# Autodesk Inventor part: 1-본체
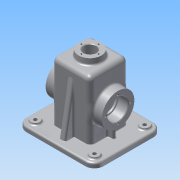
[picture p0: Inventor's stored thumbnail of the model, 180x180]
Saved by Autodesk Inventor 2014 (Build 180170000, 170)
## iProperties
Created: 2015-12
Part Number: 1-본체
Material: 알루미늄 6061
Document SubType Name: Modeling
Designer: Administrator
Density: 2.71 g/cm^3
Appearance: 알루미늄 - 평지
Mass: 804.933 g
Surface Area: 913.236 cm^2
Volume: 297.023 cm^3
Author: Administrator
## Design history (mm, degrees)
sketch "스케치1"
  geometry: L1 (-65, 57.5)-(65, 57.5); L2 (65, 57.5)-(65, -57.5); L3 (65, -57.5)-(-65, -57.5); L4 (-65, -57.5)-(-65, 57.5); L5 (-65, 57.5)-(65, -57.5); L6 (65, 57.5)-(-65, -57.5); 1 further point
  constraints: 12 end point, 2 midpoint, 2 parallel, 1 horizontal, 1 perpendicular
  dimensions: "d0" = 130 distance of L2.end L3.end; "d1" = 115 distance of L1.end L2.end
extrude "돌출1" new body sketch "스케치1" distance "d2" = 8; taper "d3" = 0 deg
sketch "스케치2"
  geometry: L1 (-60, 52.5)-(60, 52.5); L2 (60, 52.5)-(60, -52.5); L3 (60, -52.5)-(-60, -52.5); L4 (-60, -52.5)-(-60, 52.5); L5 (-60, 52.5)-(60, -52.5); L6 (60, 52.5)-(-60, -52.5); 1 further point
  constraints: 12 end point, 2 midpoint, 2 parallel, 1 horizontal, 1 perpendicular
  dimensions: "d4" = 120 distance of L2.end L3.end; "d5" = 105 distance of L1.end L2.end
extrude "돌출2" join sketch "스케치2" distance "d6" = 2; taper "d7" = 0 deg
sketch "스케치3"
  geometry: C1 r 7.5 at (-50, 42.5); C2 r 7.5 at (50, 42.5); 1 further point
  constraints: 2 centre point
  dimensions: "d8" = 15 diameter of C1; "d9" = 15 diameter of C2; "d12" = 42.5 vertical distance of C2.centre point (0, 0); "d13" = 50 horizontal distance of point (0, 0) C2.centre; "d14" = 50 horizontal distance of point (0, 0) C1.centre; "d15" = 42.5 vertical distance of point (0, 0) C1.centre
extrude "돌출3" join sketch "스케치3" distance "d16" = 3; taper "d17" = 0 deg
sketch "스케치4"
  geometry: C1 r 7.5 at (0, 0) reference; C2 r 3 at (0, 0); 1 further point
  constraints: 1 centre point, 1 coincident
  dimensions: "d18" = 6 diameter of C2
extrude "돌출4" cut sketch "스케치4" distance "d19" = 20; taper "d20" = 0 deg
sketch "스케치5"
  geometry: C1 r 7.5 at (0, 0) reference; C2 r 3 at (0, 0); 1 further point
  constraints: 1 centre point, 1 coincident
  dimensions: "d21" = 6 diameter of C2
extrude "돌출5" cut sketch "스케치5" distance "d22" = 20; taper "d23" = 0 deg
sketch "스케치6"
  geometry: L1 (-32.5, 32.5)-(32.5, 32.5); L2 (32.5, 32.5)-(32.5, -32.5); L3 (32.5, -32.5)-(-32.5, -32.5); L4 (-32.5, -32.5)-(-32.5, 32.5); L5 (-32.5, 32.5)-(32.5, -32.5); L6 (32.5, 32.5)-(-32.5, -32.5); 1 further point
  constraints: 12 end point, 2 midpoint, 2 parallel, 1 horizontal, 1 perpendicular
  dimensions: "d24" = 65 distance of L2.end L3.end; "d25" = 65 distance of L1.end L2.end
extrude "돌출6" join sketch "스케치6" distance "d26" = 100; taper "d27" = 0 deg
sketch "스케치7"
  geometry: C1 r 20 at (0, 0); 1 further point
  constraints: 1 centre point, 1 coincident
  dimensions: "d28" = 40 diameter of C1
extrude "돌출7" join sketch "스케치7" distance "d29" = 10; taper "d30" = -5 deg
sketch "스케치8"
  geometry: L1 (-10, -20)-(-10, 85) reference; L2 (-8, 90)-(0, 90) reference; C1 r 27.5 at (45, 32.5); 1 further point
  constraints: 1 centre point
  dimensions: "d31" = 55 diameter of C1; "d32" = 55 distance from line of C1.centre L1; "d34" = 57.5 distance from line of C1.centre L2
extrude "돌출8" join sketch "스케치8" distance "d35" = 15; taper "d36" = 0 deg
sketch "스케치9"
  geometry: L1 (8, 90)-(0, 90) reference; L2 (10, 85)-(10, -20) reference; C1 r 27.5 at (-45, 32.5); 1 further point
  constraints: 1 centre point
  dimensions: "d37" = 55 diameter of C1; "d38" = 57.5 distance from line of C1.centre L1; "d39" = 55 distance from line of L2 C1.centre
extrude "돌출9" join sketch "스케치9" distance "d40" = 15; taper "d41" = 0 deg
fillet "모깎기5" dims "d99" = 3
sketch "스케치10"
  geometry: L1 (57.5, 8)-(57.5, 0) reference; L2 (57.5, 0)-(52.5, 0) reference; L3 (52.5, 0)-(52.5, -2) reference; L4 (52.5, -2)-(-52.5, -2) reference; L5 (-52.5, -2)-(-52.5, 0) reference; L6 (-52.5, 0)-(-57.5, 0) reference; L7 (-57.5, 0)-(-57.5, 8) reference; L8 (-57.5, 8)-(-32.5, 8) reference; L9 (-32.5, 8)-(-32.5, 108) reference; L10 (-32.5, 108)-(-20, 108) reference; L11 (-20, 108)-(-19.125, 118) reference; L12 (-19.125, 118)-(19.125, 118) reference; L13 (19.125, 118)-(20, 108) reference; L14 (20, 108)-(32.5, 108) reference; L15 (32.5, 108)-(32.5, 8) reference; L16 (32.5, 8)-(57.5, 8) reference; L17 (-47.5, 8)-(-32.5, 93.069); 1 further point
  constraints: 2 end point, 2 point on line
  dimensions: "d42" = 10 distance from line of L17.start L7; "d43" = 100 deg angle of L17 L8
extrude "돌출10" join sketch "스케치10" stored distance "d44" = 10; taper "d45" = 0 deg
sketch "스케치11"
  geometry: L1 (-27.5, 27.5)-(27.5, 27.5); L2 (27.5, 27.5)-(27.5, -27.5); L3 (27.5, -27.5)-(-27.5, -27.5); L4 (-27.5, -27.5)-(-27.5, 27.5); L5 (-27.5, 27.5)-(27.5, -27.5); L6 (27.5, 27.5)-(-27.5, -27.5); 1 further point
  constraints: 12 end point, 2 midpoint, 2 parallel, 1 horizontal, 1 perpendicular
  dimensions: "d46" = 55 distance of L2.end L3.end; "d47" = 55 distance of L1.end L2.end
extrude "돌출11" cut sketch "스케치11" distance "d48" = 110; taper "d49" = 0 deg
sketch "스케치12"
  geometry: L1 (-42.5, 25.5)-(-42.5, 8); L2 (-60, -2)-(-60, 0) reference; L3 (-60, 0)-(-65, 0) reference; L4 (-65, 0)-(-65, 8) reference; L5 (-65, 8)-(-32.5, 8) reference; L6 (-32.5, 8)-(-32.5, 22.5) reference; L7 (-35.5, 25.5)-(-47.5, 25.5) reference; L8 (-47.5, 25.5)-(-47.5, 80.5) reference; L9 (-47.5, 80.5)-(-35.5, 80.5) reference; L10 (-32.5, 108)-(-27.5, 108) reference; L11 (-20, 108)-(-19.125, 118) reference; L12 (-19.125, 118)-(19.125, 118) reference; L13 (19.125, 118)-(20, 108) reference; L14 (27.5, 108)-(32.5, 108) reference; L15 (35.5, 80.5)-(47.5, 80.5) reference; L16 (47.5, 80.5)-(47.5, 25.5) reference; L17 (47.5, 25.5)-(35.5, 25.5) reference; L18 (32.5, 22.5)-(32.5, 8) reference; L19 (32.5, 8)-(65, 8) reference; L20 (65, 8)-(65, 0) reference; L21 (65, 0)-(60, 0) reference; L22 (60, 0)-(60, -2) reference; L23 (60, -2)-(27.5, -2) reference; L24 (27.5, -2)-(27.5, 108) reference; L25 (-27.5, 108)-(-27.5, -2) reference; L26 (-27.5, -2)-(-60, -2) reference; L27 (-32.5, 83.5)-(-32.5, 108) reference; L28 (32.5, 108)-(32.5, 83.5) reference; L29 (20, 108)-(-20, 108) reference; A1 r 3 centre (-35.5, 22.5) between (-32.5, 22.5) and (-35.5, 25.5) reference; A2 r 3 centre (35.5, 83.5) between (32.5, 83.5) and (35.5, 80.5) reference; 5 further points
  constraints: 2 end point, 2 point on line, 1 vertical, 2 other
  dimensions: "d51" = 15 distance between parallel lines of L25 L1
extrude "돌출12" join sketch "스케치12" stored distance "d52" = 6; taper "d53" = 0 deg
sketch "스케치13"
  geometry: C1 r 19.125 at (0, 0) reference; C2 r 10.5 at (0, 0)
  constraints: 1 centre point, 1 coincident
  dimensions: "d54" = 21 diameter of C2
extrude "돌출13" cut sketch "스케치13" distance "d55" = 20; taper "d56" = 0 deg
sketch "스케치14"
  geometry: C1 r 27.5 at (0, 0) reference; C2 r 17.5 at (0, 0); 1 further point
  constraints: 1 centre point, 1 coincident
  dimensions: "d57" = 35 diameter of C2
extrude "돌출14" cut sketch "스케치14" distance "d58" = 17; taper "d59" = 0 deg
sketch "스케치15"
  geometry: C1 r 27.5 at (0, 0) reference; C2 r 17.5 at (0, 0); 1 further point
  constraints: 1 centre point, 1 coincident
  dimensions: "d60" = 35 diameter of C2
extrude "돌출15" cut sketch "스케치15" distance "d61" = 17; taper "d62" = 0 deg
sketch "스케치16"
  geometry: C1 r 17.5 at (0, 0) reference; C2 r 15 at (0, 0); 1 further point
  constraints: 1 centre point, 1 coincident
  dimensions: "d63" = 30 diameter of C2
extrude "돌출16" cut sketch "스케치16" distance "d64" = 3; taper "d65" = 0 deg
sketch "스케치17"
  geometry: C1 r 17.5 at (0, 0) reference; C2 r 15 at (0, 0); 1 further point
  constraints: 1 centre point, 1 coincident
  dimensions: "d66" = 30 diameter of C2
extrude "돌출17" cut sketch "스케치17" distance "d67" = 3; taper "d68" = 0 deg
sketch "스케치18"
  geometry: C1 r 10.5 at (0, 0) reference; 1 further point
  constraints: 1 vertical alignment
  dimensions: "d69" = 14.5 distance of point (0, 14.5) C1.centre
hole "구멍1" sketch "스케치18" at (0, 14.5) diameter "d70" = 2.459; stored, may be unused: countersink angle "d74" = 90 deg, drill point angle "d76" = 118 deg; dims "d71" = 7, "d72" = 4, "d73" = 2, "d75" = 9
sketch "스케치19"
  geometry: C1 r 17.5 at (0, 0) reference; 2 further points
  constraints: 1 horizontal alignment
  dimensions: "d80" = 21 distance of point (21, 0) C1.centre
hole "구멍2" sketch "스케치19" at (21, 0) diameter "d81" = 3.459; stored, may be unused: countersink angle "d85" = 90 deg, drill point angle "d87" = 118 deg; dims "d82" = 8, "d83" = 4, "d84" = 2, "d86" = 10
sketch "스케치20"
  geometry: L1 (-100, 65)-(0, 65) reference; L2 (10, 51.625)-(10, 13.375) reference; 2 further points
  constraints: 1 other
  dimensions: "d91" = 32.5 distance from line of point (-16, 32.5) L1; "d92" = 26 distance from line of L2 point (-16, 32.5)
feature "엠보싱1" sketch "스케치20" dims "d15" = 42.5, "d93" = 0.5, "d94" = 0
sketch "스케치21"
  geometry: L1 (27.5, 27.5)-(27.5, -27.5) reference; L2 (27.5, -27.5)-(-27.5, -27.5) reference; L3 (-27.5, -27.5)-(-27.5, 27.5) reference; L4 (-27.5, 27.5)-(27.5, 27.5) reference; 1 further point
extrude "돌출18" join sketch "스케치21" distance "d117" = 5; taper "d118" = 0 deg
sketch "스케치22"
  geometry: C1 r 10.5 at (0, 0) reference
extrude "돌출19" cut sketch "스케치22" distance "d119" = 5; taper "d120" = 0 deg
fillet "모깎기20" dims "d121" = 8
fillet "모깎기21" dims "d122" = 8
fillet "모깎기22" dims "d123" = 3
fillet "모깎기23" dims "d124" = 3
fillet "모깎기24" dims "d125" = 3
fillet "모깎기25" dims "d126" = 1
fillet "모깎기26" dims "d127" = 15
fillet "모깎기27" dims "d128" = 10
fillet "모깎기28" dims "d129" = 3
fillet "모깎기29" dims "d130" = 3
fillet "모깎기30" dims "d131" = 3
chamfer "모따기2" distance "d132" = 1; stored, may be unused: second distance "d133" = 2, angle "d134" = 45 deg
fillet "모깎기31" dims "d135" = 3
fillet "모깎기32" dims "d136" = 0.3
node "솔리드1"
mirror "대칭1"
mirror "대칭2"
mirror "대칭3"
pattern_circular "원형 패턴1" dims angle "d78" = 360 deg
pattern_circular "원형 패턴2" dims angle "d89" = 360 deg
mirror "대칭4"
node "절단 모서리 투영1"
node "절단 모서리 투영2"
